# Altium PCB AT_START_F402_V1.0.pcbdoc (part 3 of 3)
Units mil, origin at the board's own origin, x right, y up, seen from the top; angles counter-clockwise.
Board outline 15424.54 x 3536.36 mil, 2 copper layers (Top Layer, Bottom Layer); 138 components, 133 nets, 522 pads, 730 vias.
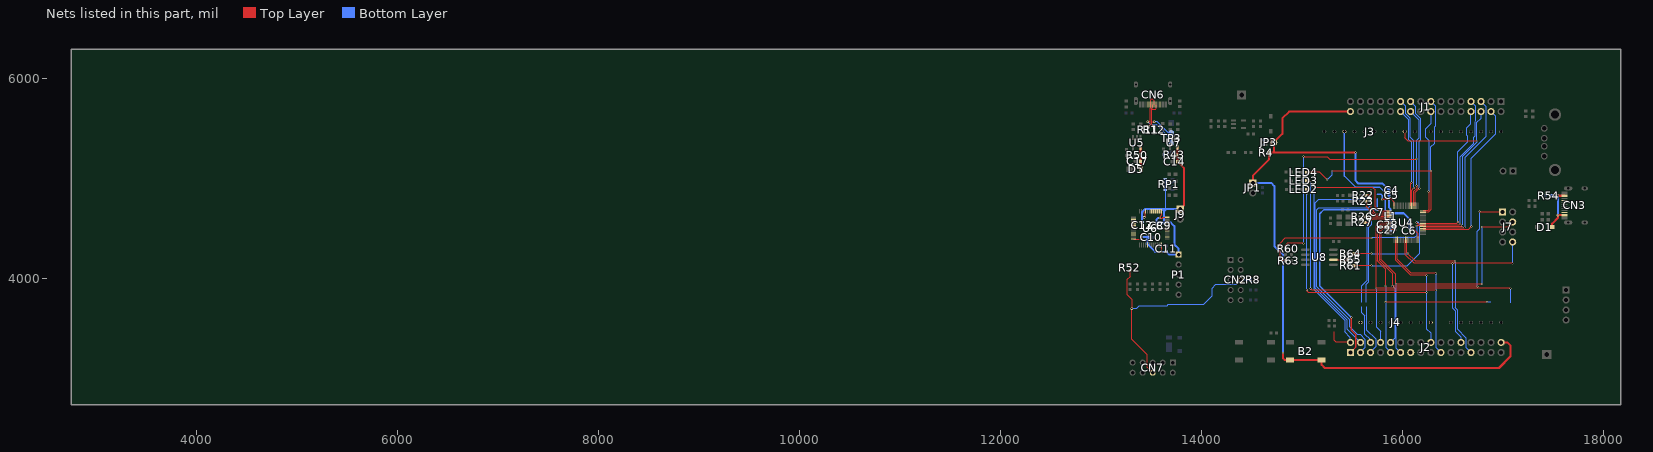
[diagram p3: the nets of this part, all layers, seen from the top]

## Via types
v1: diameter 19.68, hole 11.81, Top Layer to Bottom Layer, 621 vias
v2: diameter 19.69, hole 11.81, Top Layer to Bottom Layer, 42 vias
v3: diameter 19.7, hole 11.81, Top Layer to Bottom Layer, 26 vias
v4: diameter 23.62, hole 11.81, Top Layer to Bottom Layer, 17 vias
v5: diameter 27.56, hole 13.78, Top Layer to Bottom Layer, 15 vias
v6: diameter 24, hole 12, Top Layer to Bottom Layer, 7 vias
v7: diameter 27.56, hole 15.75, Top Layer to Bottom Layer, 2 vias

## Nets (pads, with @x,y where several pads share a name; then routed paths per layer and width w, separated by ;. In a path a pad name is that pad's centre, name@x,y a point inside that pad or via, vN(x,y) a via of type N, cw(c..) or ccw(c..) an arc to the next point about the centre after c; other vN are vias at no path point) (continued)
PB15: J1.4 U4.36 | length 1755.5
  Top Layer w6: U4.36@16206.86,4488.69 16654.71,4488.69 v1(16688.58,4522.56)
  Bottom Layer w6: v1(16688.58,4522.56) 16688.58,5200.56 16926.58,5438.56 16926.58,5622.73 J1.4@16883.44,5665.86
PC0: J2.8 U4.8 | length 2802.9
  Top Layer w6: U4.8@15868.28,4567.44 15779.45,4567.44 15739.58,4527.56 v1(15739.58,3907.2) 17075.94,3907.2 v1(17076.58,3906.57)
  Bottom Layer w6: v1(15739.58,3907.2) 15739.58,3522.95 15783.88,3478.65 J2.8@15783.88,3368.14 ; 17076.58,3763.97 v1(17076.58,3906.57)
PC1: J2.9 U4.9 | length 2479.8
  Top Layer w6: v1(15834.61,3768.57) v2(16842.58,3768.57) ; v1(15834.58,3928.57) 15834.58,4096.56 15752.58,4178.56 15752.58,4511.56 15792.7,4551.69 U4.9@15868.28,4551.69
  Bottom Layer w6: v1(15834.58,3928.57) v1(15834.61,3768.57) 15834.58,3317.45 J2.9@15883.88,3268.14 ; v2(16842.58,3768.57) 16880.08,3768.57 ; 16878.83,3769.82 16880.08,3768.57 ; 16881.83,3766.82 16880.08,3768.57
PC2: J2.10 J7.1 U4.10 | length 3155.1
  Top Layer w6: U4.10@15868.28,4535.94 15805.96,4535.95 15768.58,4498.56 15768.58,4187.56 15903.58,4052.57 v1(15903.58,3927.57) 16745.58,3927.57 v1(16746.58,3926.57) ; v1(16766.58,4669.56) 16996.47,4669.56 J7.1@16998.88,4667.16
  Bottom Layer w6: J2.10@15883.88,3368.14 15924.58,3408.84 15924.58,3906.57 v1(15903.58,3927.57) ; v1(16746.58,3926.57) 16746.58,4474.05 16766.58,4494.05 v1(16766.58,4669.56)
PC3: J2.11 J7.4 U4.11 | length 3150.1
  Top Layer w6: U4.11@15868.28,4520.19 15825.2,4520.19 15784.58,4479.56 15784.58,4197.03 15936.58,4045.03 v1(15936.58,3947.79) ; v1@15934.58,3949.79 v1(15936.58,3947.79) ; v1(16795.28,4517.56) 17049.28,4517.56 J7.4@17098.88,4567.16 ; v1(16795.58,3948.57) 16794.58,3947.57 15936.8,3947.57 v1(15936.58,3947.79)
  Bottom Layer w6: v1(15936.58,3947.79) 15936.58,3315.45 J2.11@15983.88,3268.14 ; v1(16795.28,4517.56) 16795.28,3948.86 v1(16795.58,3948.57)
PC4: J2.24 J7.8 U4.24 | length 2289.3
  Top Layer w6: U4.24@16029.7,4390.27 16029.7,4241.44 16116.58,4154.56 v2(16498.58,4154.56) v1(17099.58,4154.56)
  Bottom Layer w6: v2(16498.58,4154.56) 16498.58,3713.57 16526.58,3685.57 16526.58,3480.03 16583.88,3422.74 J2.24@16583.88,3368.14 ; J7.8@17098.88,4367.16 17099.58,4366.47 v1(17099.58,4154.56)
PC5: J2.25 R64.1 U4.25 | length 2155.2
  Top Layer w6: R64.1@15516.58,4251.56 v3(15691.58,4251.56) ; U4.25@16045.45,4390.27 16045.45,4261.69 v3(16055.57,4251.57) 16133.58,4173.56 v2(16525.58,4173.56)
  Bottom Layer w6: v3(15691.58,4251.56) v3(16055.57,4251.57) ; v2(16525.58,4173.56) 16525.58,3714.43 16544.58,3695.43 16544.58,3503.7 16632.58,3415.7 16632.58,3319.43 J2.25@16683.88,3268.14
PC6: J1.5 U4.37 | length 1773.5
  Top Layer w6: U4.37@16206.86,4504.44 16609.46,4504.44 v1(16619.58,4514.56)
  Bottom Layer w6: v1(16619.58,4514.56) 16619.58,5207.56 16828.58,5416.56 16828.58,5720.73 J1.5@16783.44,5765.86
PC7: J1.6 J3.2 U4.38 | length 2399.2
  Top Layer w6: J3.2@16023.88,5466.56 16023.88,5407.49 16060.81,5370.56 v2(16742.58,5370.56) ; U4.38@16206.86,4520.19 16585.21,4520.2 v1(16596.42,4531.41)
  Bottom Layer w6: v1(16596.42,4531.41) 16596.42,5215.93 16742.58,5362.08 v2(16742.58,5370.56) 16742.58,5559.56 16783.44,5600.44 J1.6@16783.44,5665.86
PC8: J1.7 R63.1 U4.39 | length 3447.9
  Top Layer w6: R63.1@14837.92,4181.56 14807.58,4181.56 14782.58,4206.56 14782.58,4355.56 14834.58,4407.56 v3(15691.58,4407.56) ; v3(16141.58,4525.56) 16151.95,4535.94 U4.39@16206.86,4535.94 16561.96,4535.95 v1(16575.22,4549.21)
  Bottom Layer w6: v3(15691.58,4407.56) 16119.58,4407.56 16141.58,4429.56 v3(16141.58,4525.56) ; v1(16575.22,4549.21) 16575.22,5218.21 16708.87,5351.85 16708.87,5408.23 16726.58,5425.94 16726.58,5566.56 16733.58,5573.56 16733.58,5717.56 16685.28,5765.86 J1.7@16683.44,5765.86
PC9: J1.8 R61.1 U4.40 | length 2627
  Top Layer w6: R61.1@15515.9,4131.56 v3(15692.58,4131.56) ; v3(16140.58,4562.56) 16151.45,4551.69 U4.40@16206.86,4551.69 16538.7,4551.69 v2(16553.58,4566.56)
  Bottom Layer w6: v3(15692.58,4131.56) 16051.58,4131.56 16173.58,4253.56 16173.58,4545.56 16156.58,4562.56 v3(16140.58,4562.56) ; v2(16553.58,4566.56) 16553.58,5265.56 16652.58,5364.56 16652.58,5418.56 16640.58,5430.56 16640.58,5503.56 16683.44,5546.44 J1.8@16683.44,5665.86
PC10: J1.19 U4.51 | length 1103.9
  Top Layer w6: U4.51@16124.19,4728.85 16124.19,4856.18 v2(16170.58,4902.56)
  Bottom Layer w6: J1.19@16083.44,5765.86 16134.58,5714.73 16134.58,5642.56 16184.58,5592.56 16184.58,5386.56 16170.58,5372.56 v2(16170.58,4902.56)
PC11: J1.20 R60.1 U4.52 | length 3218.6
  Top Layer w6: R60.1@14836.92,4300.56 14836.92,4334.9 14856.58,4354.56 v3(15015.58,4354.56) ; v3(15015.58,5217.56) 15253.58,5217.56 15278.49,5192.65 v3(16142.58,5192.65) ; U4.52@16108.44,4728.85 16108.44,4865.44 16142.58,4899.56 v2(16142.58,4930.56)
  Bottom Layer w6: v3(15015.58,4354.56) v3(15015.58,5217.56) ; J1.20@16083.44,5665.86 16168.58,5580.73 16168.58,5404.56 16142.58,5378.56 v3(16142.58,5192.65) v2(16142.58,4930.56)
PC12: J1.21 U4.53 | length 1100.4
  Top Layer w6: U4.53@16092.69,4728.85 16092.69,4884.68 v2(16114.58,4906.56)
  Bottom Layer w6: J1.21@15983.44,5765.86 16032.58,5716.73 16032.58,5644.56 16078.58,5598.56 16078.58,5412.56 16114.58,5376.56 v2(16114.58,4906.56)
PC13: J2.2 U4.2 | length 2911.7
  Top Layer w6: v1(15116.58,4912.56) 15702.58,4912.56 15728.58,4886.56 15728.58,4719.56 15786.22,4661.93 U4.2@15868.28,4661.93 ; 15317.85,3474.57 15322.76,3474.57 15320.58,3472.38 15320.58,3391.57 15344,3368.14 J2.2@15483.88,3368.14
  Bottom Layer w6: v1(15116.58,4912.56) 15116.58,3896.57 15425.58,3587.57 15425.58,3472.57 15483.88,3414.27 J2.2@15483.88,3368.14
PC14: J2.3 | length 2278.3
  Bottom Layer w6: J2.3@15583.88,3268.14 15633.58,3317.84 15633.58,3396.57 15586.58,3443.57 15554.58,3443.57 15475.58,3522.57 15475.58,3593.57 15147.58,3921.57 15147.58,4688.56 15169.58,4710.56 15659.58,4710.56 15689.58,4740.56 15689.58,4794.28
PC14/LEXT_IN: R22.1 U4.3 | length 480.3
  Top Layer w6: R22.1@15637.08,4832.56 15688.55,4832.56 ; v1(15688.58,4881.56) 15688.58,4696.56 15738.96,4646.18 U4.3@15868.28,4646.18
  Bottom Layer w6: v1(15688.58,4881.56) 15689.58,4880.56 15689.58,4838.69
PC15: J2.4 | length 2051.5
  Bottom Layer w6: J2.4@15583.58,3368.57 15450.58,3501.57 15450.58,3590.57 15132.58,3908.57 15132.58,4756.68 15170.18,4794.28 15593.58,4794.28
PC15/LEXT_OUT: R23.1 U4.4 | length 448.6
  Top Layer w6: R23.1@15639.08,4774.56 v1(15639.08,4739.92) 15639.08,4722.06 15730.71,4630.43 U4.4@15868.28,4630.43
  Bottom Layer w6: 15605.58,4838.69 15605.69,4838.56 15633.58,4838.56 15639.08,4833.06 v1(15639.08,4739.92)
PD2: J1.22 U4.54 | length 988.3
  Top Layer w6: U4.54@16076.94,4728.85 16076.94,4942.93 v2(16092.58,4958.56)
  Bottom Layer w6: J1.22@15983.58,5665.56 16064.58,5584.56 16064.58,5387.45 16092.58,5359.45 v2(16092.58,4958.56)
PF0: J2.5 | length 511.8
  Bottom Layer w6: 15643.58,3721.28 15642.58,3720.28 15642.58,3495.57 15733.58,3404.57 15733.58,3323.57 15683.88,3273.86 J2.5@15683.88,3268.14
PF0/HEXT_IN: R26.1 U4.5 | length 1120.8
  Top Layer w6: R26.1@15628.08,4616.56 15629.17,4615.47 v1(15671.97,4615.33) U4.5@15868.28,4614.69
  Bottom Layer w6: 15643.58,3765.68 15643.58,3948.57 15665.58,3970.57 15665.58,4513.56 15694.58,4542.56 15694.58,4592.72 v1(15671.97,4615.33)
PF1: J2.6 | length 393.2
  Bottom Layer w6: 15589.58,3722.28 15589.58,3670.57 15628.58,3631.57 15628.58,3447.57 15683.88,3392.26 J2.6@15683.88,3368.14
PF1/HEXT_OUT: R27.1 U4.6 | length 1084.7
  Top Layer w6: R27.1@15628.08,4562.56 v1(15670.58,4562.56) 15706.94,4598.94 U4.6@15868.28,4598.94
  Bottom Layer w6: 15589.58,3766.68 15589.58,3925.57 15647.58,3983.57 15647.58,4539.56 v1(15670.58,4562.56)
PF4: J2.18 LED2.2 U4.18 | length 3464.8
  Top Layer w6: v1(15049.23,3891.48) 15049.23,3881.04 15064.35,3865.91 v1(16240.58,3865.91) ; v1(15049.23,4849.22) 15049.53,4849.52 LED2.2@15049.53,4890.77 ; U4.18@15935.22,4390.27 15935.22,4185.93 16085.58,4035.57 v2(16240.58,4035.57)
  Bottom Layer w6: v1(15049.23,3891.48) v1(15049.23,4849.22) ; v2(16240.58,4035.57) v1(16240.58,3865.91) 16240.58,3506.57 16283.88,3463.28 J2.18@16283.88,3368.14
PF5: J2.19 LED3.2 U4.19 | length 3807.3
  Top Layer w6: LED3.2@15049.53,4976.77 v1(15085.37,4976.77) ; v1(15085.37,3904.35) 15102.48,3887.25 v1(16333.58,3887.25) ; U4.19@15950.97,4390.27 15950.97,4195.18 16090.58,4055.57 v2(16333.58,4055.57)
  Bottom Layer w6: v1(15085.37,3904.35) v1(15085.37,4976.77) ; v2(16333.58,4055.57) v1(16333.58,3887.25) 16333.58,3318.43 J2.19@16383.88,3268.14
PF6: J1.15 LED4.2 U4.47 | length 2527.9
  Top Layer w6: LED4.2@15049.53,5060.77 15179.37,5060.77 v1(15251.58,4988.56) ; v1(15302.58,5074.56) v2(16284.58,5074.56) 16284.58,4687.56 16258.93,4661.93 U4.47@16206.86,4661.93
  Bottom Layer w6: v1(15251.58,4988.56) 15302.58,5039.56 v1(15302.58,5074.56) ; J1.15@16283.44,5765.86 16332.58,5716.73 16332.58,5522.56 16322.58,5512.56 16322.58,5352.56 16284.58,5314.56 v2(16284.58,5074.56)
PF7: J1.16 U4.48 | length 1073.3
  Top Layer w6: U4.48@16206.86,4677.68 16252.69,4677.68 16261.58,4686.56 v2(16261.58,4870.56)
  Bottom Layer w6: v2(16261.58,4870.56) 16262.58,4871.56 16262.58,5382.56 16230.58,5414.56 16230.58,5490.56 16283.44,5543.44 J1.16@16283.44,5665.86
SCK: R65.2 U8.6 | length 143.2
  Top Layer w6: U8.6@15314.03,4191.56 R65.2@15457.25,4191.56
SWO: CN2.6 CN7.6 R8.2 R52.1 | length 2484.5
  Top Layer w6: R52.1@13290.15,4081.97 13290.15,4024.01 13256.58,3990.45 13256.58,3846.57 13306.58,3796.57 v4(13306.58,3704.57) 13306.58,3399.57 13462.58,3243.57 13462.58,3119.78 CN7.6@13515.34,3067.01
  Bottom Layer w6: v4(13306.58,3704.57) 13350.58,3704.57 13374.58,3728.57 13653.58,3728.57 13665.58,3740.57 14016.58,3740.57 14101.58,3825.57 14101.58,3904.57 14139.58,3942.57 14343.65,3942.57 CN2.6@14390.92,3989.84 ; CN2.6@14390.97,3989.89 R8.2@14490.58,3989.89
USB+: CN6.A6 CN6.B6 R11.1 TP3.3 | length 723.2
  Top Layer w11.2: v5(13466.68,5563.67) 13490.33,5563.67 ; R11.1@13469.58,5515.56 13490.33,5536.31 13490.33,5563.67 ; CN6.A6@13528.38,5735.27 13528.38,5774.77 13516.58,5786.56 13499.58,5786.56 13489.58,5776.56 13489.58,5735.77 CN6.B6@13489.08,5735.27 13489.08,5699.11 13490.33,5697.86 13490.33,5563.67
  Bottom Layer w11.2: v5(13466.68,5563.67) 13497.78,5532.56 13553.58,5532.56 13699.92,5386.22 TP3.3@13699.92,5351.02
USB-: CN6.A7 CN6.B7 R12.1 TP3.2 | length 554.9
  Top Layer w11.2: CN6.A7@13508.77,5735.27 13508.77,5699.11 13507.52,5697.86 13507.52,5683.94 ; R12.1@13528.58,5515.23 13507.52,5536.27 13507.52,5563.67 ; v5(13531.68,5563.67) 13507.52,5563.67 ; CN6.B7@13548.08,5735.27 13548.08,5693.06 13539.58,5684.56 13508.15,5684.56 13507.52,5683.94 ; 13507.52,5563.67 13507.52,5683.94
  Bottom Layer w11.2: v5(13531.68,5563.67) 13561.47,5563.67 13674.12,5451.02 TP3.2@13699.92,5451.02
VBUS_FS: CN3.A4B9 CN3.B4A9 D1.1 R54.2 | length 531.4
  Top Layer w20: D1.1@17492.58,4515.56 17492.58,4550.28 17549.08,4606.78 v6(17549.08,4635.06) CN3.A4B9@17615.28,4635.06 ; v6(17549.08,4827.06) 17550.08,4828.06 CN3.B4A9@17615.28,4828.06
  Bottom Layer w6: R54.2@17485.58,4827.56 v6@17548.58,4827.56
  Bottom Layer w20: v6@17548.58,4827.56 v6(17549.08,4827.06) v6(17549.08,4635.06)
VCC: C8.1 C9.1 C10.1 C11.1 C12.1 C14.1 J9.1 P1.1 R43.2 RP1.1 RP1.2 RP1.3 RP1.4 U6.1 U6.9 U6.24 U6.36 U6.48 U7.5 | length 3073.1
  Top Layer w10: U6.24@13324.5,4397.43 13390.33,4397.43 v4(13407.92,4415.02) ; v4(13430.58,4612.56) 13442.6,4624.6 U6.9@13442.6,4673.02 ; U6.36@13600.08,4338.36 13600.08,4270.27 v4(13600.34,4270.02) ; U6.1@13600.08,4673.02 13600.08,4632.76 13583.34,4616.02 v4(13583.34,4606.02) 13612.34,4606.02 13620.3,4613.97 U6.48@13659.15,4613.97
  Top Layer w20: C14.1@13764.14,5165.56 13827.58,5102.12 13827.58,4732.16 J9.1@13789.38,4693.97 ; C14.1@13764.34,5166.3 U7.5@13764.34,5307.9
  Bottom Layer w10: 13638.82,4683.98 13640.58,4685.73 13640.58,4694.02 RP1.1@13640.58,4887.56 RP1.2@13640.58,4922.99 RP1.3@13640.58,4958.44 RP1.4@13640.58,4993.86
  Bottom Layer w20: C12.1@13407.34,4560.02 13407.34,4664.02 13437.34,4694.02 13610.53,4694.02 ; 13407.35,4614.02 13429.12,4614.02 v4(13430.58,4612.56) ; v4(13407.92,4415.02) 13465.34,4415.02 13465.34,4345.02 13540.34,4270.02 v4(13600.34,4270.02) 13650.58,4273.06 13681.08,4242.56 P1.1@13772.58,4242.56 13772.58,4300.56 13730.34,4342.8 13730.34,4526.02 13696.34,4560.02 C9.1@13628.34,4560.02 ; v4(13583.34,4606.02) 13567.34,4606.02 13554.34,4593.02 13554.34,4560.02 C9.1@13628.34,4560.02 ; J9.1@13789.34,4694.02 13649.06,4694.02 ; 13610.53,4694.02 13610.53,4691.52 13628.34,4673.7 ; 13610.53,4694.02 13640.58,4694.02 13649.06,4694.02 ; C9.1@13628.34,4560.02 13628.34,4673.7 ; 13628.34,4673.7 13638.82,4683.98 13649.06,4694.02
VCC3.5V: C17.1 D5.2 R50.2 U5.5 | length 488.1
  Top Layer w20: U5.5@13395.58,5305.56 13395.15,5110.74 D5.2@13396.33,5109.56
  Top Layer w25: D5.2@13389.33,5099.56 D5.2@13395.14,5105.38 ; U5.5@13395.14,5305.9 C17.1@13395.14,5173.56 ; D5.2@13397.33,5091.56 13395.14,5093.76 D5.2@13395.14,5105.38 ; D5.2@13395.15,5105.39 13395.15,5110.74 C17.1@13395.14,5173.56 ; D5.2@13395.14,5105.38 C17.1@13395.14,5173.56
VDD: B2.1 B2.2 C4.1 C5.1 C6.1 C7.1 J1.32 J2.1 J2.32 JP1.1 JP3.2 L1.1 R4.1 U4.1 U4.32 U4.64 | length 10874.9
  Top Layer w8: v1(15792.58,4690.56) 15805.47,4677.68 U4.1@15868.28,4677.68 ; v1(15869.11,4792.31) 15869.37,4792.56 15892.58,4792.56 15919.47,4765.68 U4.64@15919.47,4728.85 ; v1(16108.58,4499.56) 16155.68,4452.45 U4.32@16155.68,4403.27
  Top Layer w15: J2.1@15483.88,3268.14 15534.58,3318.84 15534.58,3446.57 15493.58,3487.57 v1(15493.58,3614.57) ; v1@15799.58,4792.56 v1(15799.83,4792.31) v1(15869.11,4792.31)
  Top Layer w20: JP1.1@14511.57,4956.56 14511.57,5028.56 14675.08,5192.06 R4.1@14675.08,5258.56 14720.43,5258.56 14720.58,5258.71 ; v1(14813.58,3262.57) 14813.58,3209.57 14830.58,3192.57 14880.68,3192.57 B2.2@14881.09,3192.99 B2.1@15196.06,3192.99 15196.06,3144.09 15226.58,3113.57 16962.58,3113.57 17076.58,3227.57 17076.58,3338.57 17046.58,3368.57 16984.31,3368.57 J2.32@16983.88,3368.14 ; J1.32@15483.44,5665.86 14873.88,5665.86 14806.58,5598.56 14806.58,5444.56 JP3.2@14720.58,5358.57 14720.58,5258.71 ; v1(15532.72,5258.71) 14720.58,5258.71
  Bottom Layer w15: v1(15493.58,3614.57) 15177.58,3930.57 15177.58,4647.84 15216.3,4686.56 15746.08,4686.56 C7.1@15750.58,4691.06 ; 15750.58,4796.28 C7.1@15750.58,4691.06 ; 15750.58,4840.69 15790.45,4840.69 15799.83,4831.31 v1(15799.83,4792.31) ; v1(15792.58,4690.56) 15751.08,4690.56 C7.1@15750.58,4691.06
  Bottom Layer w20: JP1.1@14511.57,4956.56 14694.58,4956.56 14726.58,4924.56 14726.58,4327.56 14813.58,4240.56 v1(14813.58,3262.57) ; v1(15532.72,5258.71) 15532.72,4980.88 15564.04,4949.56 15804.08,4949.56 C4.1@15869.08,4884.56 v1(15869.11,4792.31) ; 15869.08,4809.56 v1(15869.11,4792.31) ; v1(16108.58,4499.56) 16099.08,4509.06 C6.1@16069.58,4509.06 16069.58,4598.56 16014.26,4653.88 L1.1@15884.58,4653.88 15883.58,4654.88 15883.58,4694.56 15869.11,4709.03 v1(15869.11,4792.31)
VDDA: C27.2 C28.2 J3.8 L1.2 U4.13 | length 1446
  Top Layer w9: U4.13@15868.28,4488.69 15868.41,4488.56 v2(15933.58,4488.56)
  Bottom Layer w15: J3.8@15423.88,5466.56 15423.88,5023.91 15533.22,4914.56 15773.58,4914.56 15832.58,4855.56 15832.58,4607.56 15846.9,4593.24 L1.2@15884.58,4593.24 C28.2@15884.58,4537.56 ; C27.2@15884.58,4488.56 v2(15933.58,4488.56)
  Bottom Layer w20: C27.2@15884.58,4488.56 C28.2@15884.58,4537.56
"": CN3.A8 CN3.B8 CN6.A8 CN6.B8 J2.13 J4.1 J4.8 U6.2 U6.3 U6.4 U6.5 U6.6 U6.14 U6.15 U6.16 U6.17 U6.18 U6.21 U6.22 U6.29 U6.38 U6.41 U6.42 U6.43 U6.45 U6.46

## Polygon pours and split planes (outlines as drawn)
GND on Bottom Layer (solid, remove dead copper, pour order 0): 17151.58,5987.56 17151.58,5631.4 17408.58,5629.56 17455.58,5607.56 17455.58,4872.56 17699.58,4872.56 17699.58,4588.86 17594.58,4586.56 17595.17,4511.56 17700.57,4512.19 17701.58,3042.57 13183.5,3041.64 13182.58,3042.57 13182.58,5728.56 13368.58,5728.56 13368.58,5808.56 13373.58,5813.56 13662.58,5813.56 13662.58,5732.56 13939.58,5732.56 13939.58,5984.56 13942.98,5987.97 17151.17,5987.97
GND on Bottom Layer (solid, remove dead copper, pour order 1): 17604.57,4095.86 17604.58,4095.57 17604.58,4096.56
GND on Top Layer (solid, remove dead copper, pour order 2): 17151.58,5681.37 17151.58,5632.56 17151.54,5681.37
GND on Top Layer (solid, remove dead copper, pour order 3): 17151.58,5987.56 17151.58,5632.56 17408.58,5629.56 17455.58,5607.56 17455.58,4872.56 17699.83,4872.27 17699.58,4592.56 17699.58,4588.56 17595.58,4586.56 17595.58,4511.56 17700.58,4511.56 17700.58,3970.57 17701.58,3042.57 13182.58,3042.57 13182.58,5727.56 13181.58,5728.56 13368.58,5728.56 13368.58,5793.28 13348.48,5813.38 13662.39,5813.38 13662.58,5813.56 13662.58,5732.56 13940.58,5732.56 13940.58,5985.56 13942.58,5987.56

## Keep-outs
Top Layer:
  region net "": 13642.58,4450.56 13675.58,4450.56 13675.58,4443.56 13642.58,4443.56
Board Outline Layer:
  lines w8 net "": 13799.95,3001.67 ccw(c13802.87,3080.36) 13881.61,3080.36 13881.87,3519.01 13921.13,3519.01 13921.13,3080.36 ccw(c13999.87,3080.36) 13999.87,3001.62 ; 13802.87,6030.91 cw(c13802.87,5952.17) 13881.61,5952.17 13881.61,5632.02 13921.13,5632.02 13921.13,5951.91 cw(c13999.87,5951.91) 13999.87,6030.65 ; 13920.13,4826.02 13881.87,4826.02 13881.87,3810.02 ; 13920.87,4825.28 13920.87,3810.01 13881.87,3810.01 ; 13999.24,3001.05 ccw(c13999.87,3005.02) 13999.87,3001 ; 13999.87,6031.43 ccw(c13999.9,6035.44) 13999.9,6031.43 ; 17836.3,5974.43 cw(c17836.87,5970.45) 17836.87,5974.47 ; 13881.87,3810.02 13881.87,3810.01 ; 13881.87,3607.01 13881.87,3699.01 13921.13,3699.01 13921.13,3607.01 13881.87,3607.01 ; 13881.87,4904.02 13881.87,5554.02 13921.13,5554.02 13921.13,4904.27 13920.87,4904.02 13881.87,4904.02
  lines w10 net "": 13149.49,5947.67 cw(c13153.5,5947.67) 13150.15,5949.89 cw(c13232.87,5947.41) 13231.42,6030.16 cw(c13232.87,6026.41) 13232.87,6030.43 ; 13149.49,5947.67 13149.49,5947.67 ; 13149.49,5947.67 13149.9,3082.97 ; 13149.9,3082.97 13149.9,3082.97 ; 13149.9,3082.97 ccw(c13153.92,3082.97) 13150.17,3081.52 ccw(c13232.92,3082.97) 13231.59,3000.23 ccw(c13232.92,3004.02) 13232.92,3000 ; 13232.87,6030.43 13999.81,6030.43 13999.87,6030.43 17281.13,6030.43 17836.3,6030.43 17836.87,6030.47 cw(c17836.87,5947.71) 17919.61,5949.17 cw(c17915.87,5947.71) 17919.89,5947.71 ; 13232.87,6030.43 13232.87,6030.43 ; 13232.92,3000 13232.92,3000 ; 13232.92,3000 13998.61,3000 ; 13998.61,3000 13998.61,3000 ; 13998.61,3000 ccw(c13998.61,3004.02) 13999.24,3000.05 13999.87,3000 17281.13,3000 17836.87,3000 ; 17836.87,3000 17836.87,3000 ; 17836.87,3000 ccw(c17836.87,3082.76) 17919.61,3081.3 ccw(c17915.87,3082.76) 17919.88,3082.76 ; 17919.88,3082.76 17919.88,3082.76 ; 17919.88,3082.76 17919.88,5947.72 ; 17919.88,5947.72 17919.89,5947.71

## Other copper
Top Layer:
  drawing of 487 lines, arcs and shapes, not listed
Bottom Layer:
  drawing of 388 lines, arcs and shapes, not listed

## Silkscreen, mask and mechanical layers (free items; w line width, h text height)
Top Silkscreen Layer:
  circle w50 net "": c17073.58,5765.56 r1
  circle w50 net "": c15389.58,3268.57 r1
  lines w5 net "": 16867.58,5338.56 16869.58,5338.56 ; 17005.58,5355.56 17003.58,5355.56 ; 16869.58,5338.56 16888.58,5357.56 16888.58,5362.56 ; 16869.58,5338.56 16905.58,5338.56 ; 16869.58,5338.56 16871.58,5338.56 16888.58,5355.56 ; 16888.58,5338.56 16885.58,5341.56 16874.58,5341.56 16875.58,5340.56 16880.58,5340.56 16887.08,5347.06 16888.58,5347.06 16897.08,5338.56 16905.58,5338.56 ; 16888.58,5338.56 16888.58,5355.56 ; 16888.58,5338.56 16893.58,5343.56 ; 16888.58,5355.56 16893.58,5350.56 16893.58,5343.56 ; 16888.58,5355.56 16908.58,5335.56 ; 16888.58,5355.56 16888.58,5362.56 ; 16888.58,5362.56 16886.58,5362.56 16859.58,5335.56 16908.58,5335.56 ; 16888.58,5362.56 16915.58,5335.56 16908.58,5335.56 ; 16893.58,5343.56 16900.58,5343.56 16905.58,5338.56 ; 16905.58,5338.56 16908.58,5335.56 ; 16964.58,5358.56 17013.58,5358.56 16986.58,5331.56 16984.58,5331.56 ; 16964.58,5358.56 16957.58,5358.56 16984.58,5331.56 ; 16964.58,5358.56 16967.58,5355.56 ; 16964.58,5358.56 16984.58,5338.56 ; 16967.58,5355.56 16976.08,5355.56 16984.58,5347.06 16986.08,5347.06 16992.58,5353.56 16997.58,5353.56 16998.58,5352.56 16987.58,5352.56 16984.58,5355.56 ; 16967.58,5355.56 16972.58,5350.56 16979.58,5350.56 ; 16967.58,5355.56 17003.58,5355.56 ; 16979.58,5350.56 16984.58,5355.56 ; 16979.58,5350.56 16979.58,5343.56 16984.58,5338.56 ; 16984.58,5331.56 16984.58,5338.56 ; 16984.58,5331.56 16984.58,5336.56 17003.58,5355.56 ; 16984.58,5338.56 16984.58,5355.56 ; 16984.58,5338.56 17001.58,5355.56 17003.58,5355.56
  lines w6 net "": 13364.57,3293.28 13364.57,3592.28 ; 13464.57,3294.28 13464.57,3593.28 ; 13564.57,3294.28 13564.57,3594.28 ; 13666.57,3293.28 13666.57,3587.28
  lines w8 net "": 13462.92,3219.01 13462.92,3259.01 13562.92,3259.01 13562.92,3218.01 ; 13753.47,3273.01 13716.47,3236.01 13677.47,3275.01 13753.47,3275.01 ; 14177.57,4227.19 14177.57,4151.19 14216.57,4190.19 14179.57,4227.19 ; 14240.57,3940.2 14200.57,3940.2 14200.57,4040.2 14241.57,4040.2
  lines w10 net "": 15596.17,5193.72 17011.87,5193.72 ; 15870.08,3854.57 16323.08,3854.57 ; 16458.58,3854.57 17018.58,3854.57
  text "43" at 16450.01,5950.73 h38.28
  text "33" at 16956.01,5950.73 h38.28
  text "53" at 15956.01,5948.73 h38.28
  text "63" at 15450.01,5946.73 h38.28
  text "F6" at 16277.73,5839.29 h34.45 r45
  text "A8" at 16574.84,5837.58 h34.45 r45
  text "C8" at 16672.84,5837.58 h34.45 r45
  text "C12" at 15974.55,5837.29 h34.45 r45
  text "A12*" at 16367.51,5836.98 h34.45 r45
  text "A10" at 16466.55,5837.29 h34.45 r45
  text "B7" at 15684.84,5835.58 h34.45 r45
  text "B5" at 15780.52,5835.26 h34.45 r45
  text "B3" at 15876.78,5835.28 h34.45 r45
  text "B14" at 16872.55,5835.29 h34.45 r45
  text "B8" at 15578.84,5833.58 h34.45 r45
  text "C6" at 16778.84,5833.58 h34.45 r45
  text "C10" at 16068.55,5833.29 h34.45 r45
  text "A14" at 16162.55,5833.29 h34.45 r45
  text "B12" at 16978.55,5833.29 h34.45 r45
  text "GND" at 15467.07,5826.52 h34.45 r45
  text "GND" at 14497.65,5812.28 h45.94
  text "B9" at 15572.84,5539.58 h34.45 r45
  text "F11" at 15661.9,5536.78 h28.71 r45
  text "F7" at 16271.74,5535.29 h34.45 r45
  text "D2" at 15977.46,5534.13 h34.45 r45
  text "C9" at 16674.84,5533.58 h34.45 r45
  text "C11" at 16069.87,5533.27 h34.45 r45
  text "A9" at 16574.84,5531.58 h34.45 r45
  text "C7" at 16774.84,5531.58 h34.45 r45
  text "B6" at 15774.53,5531.26 h34.45 r45
  text "B4" at 15870.8,5531.28 h34.45 r45
  text "A15" at 16168.55,5525.29 h34.45 r45
  text "B15" at 16864.55,5525.29 h34.45 r45
  text "B13" at 16976.55,5525.29 h34.45 r45
  text "A13" at 16362.55,5523.29 h34.45 r45
  text "A11*" at 16464.26,5523 h34.45 r45
  text "VDD" at 15446.55,5515.29 h34.45 r45
  text "4" at 16601.8,5362.56 h45.56 r90
  text "7" at 16313.8,5360.56 h45.56 r90
  text "2" at 16803.8,5360.56 h45.56 r90
  text "8" at 16147.8,5359.56 h45.56 r90
  text "13" at 15653.98,5333.59 h45.94 r90
  text "12" at 15747.98,5333.59 h45.94 r90
  text "IDD" at 14793.42,5328.4 h45.94
  text "#3" at 16709.98,5315.89 h45.94 r90
  text "#9" at 16047.98,5313.89 h45.94 r90
  text "#6" at 16405.98,5313.89 h45.94 r90
  text "#5" at 16509.98,5313.89 h45.94 r90
  text "#11" at 15851.98,5305.54 h45.94 r90
  text "#10" at 15947.98,5285.84 h45.94 r90
  text "HOST" at 17306.86,5274.63 h45.94 r90
  text "SCL" at 15245.98,5270.64 h45.94 r90
  text "GND" at 15547.98,5266.24 h45.94 r90
  text "SDA" at 15349.98,5264.04 h45.94 r90
  text "TX 1" at 16906.86,5234.63 h45.94 r90
  text "RX 0" at 17008.86,5231.63 h45.94 r90
  text "DIGITAL(#=PWM)" at 15992.19,5222.83 h40.19
  text "VDDA" at 15445.98,5214.18 h45.94 r90
  text "LD:" at 13803.32,5157 h40.19 r270
  text "AT-Link-EZ V1.4" at 13197.82,5072.38 h57.42 r270
  text "1" at 13803.99,5055.27 h39.87 r270
  text "FS_VBUS" at 16604.58,5055.28 h45.94
  text "2" at 13803.99,4988.27 h39.87 r270
  text "VDD" at 14300.65,4945.28 h45.95
  text "3" at 13803.99,4915.27 h39.87 r270
  text "4" at 13803.99,4840.27 h39.87 r270
  text "BOOT0" at 14204.62,4833.28 h45.94
  text "5V" at 17172.91,4650.31 h40.19
  text "MISO" at 16783.02,4648.83 h40.19
  text "Device" at 17541.86,4612.59 h45.94 r90
  text "SCK" at 16803.5,4543.83 h40.19
  text "MOSI" at 17169.02,4543.83 h40.19
  text "GND" at 17169.5,4448.83 h40.19
  text "RESET" at 16732.53,4443.83 h40.19
  text "NSS" at 16803.5,4343.83 h40.19
  text "PC4" at 17169.78,4338.83 h40.19
  text "AT-Link" at 14180.76,4295.65 h57.42
  text "5V" at 14477.98,4173.83 h40.19
  text "3V3" at 14041.5,4167.83 h40.19
  text "SWD" at 14045.5,4073.83 h40.19
  text "BOOT0" at 14476.53,4068.83 h40.19
  text "SWO" at 14477.5,3968.83 h40.19
  text "SWC" at 14042.5,3958.83 h40.19
  text "AT-START-F402 V1.0" at 16034.71,3911.41 h69.7
  text "3V3" at 17437.83,3868.83 h40.19
  text "USART1_RX" at 14474.6,3863.83 h40.19
  text "NRST" at 14047.02,3858.83 h40.19
  text "POWER" at 16104.53,3790.83 h40.19
  text "ANALOG IN" at 16606.6,3790.83 h40.19
  text "USART1_TX" at 17201.23,3772.83 h40.19
  text "GND" at 14047.5,3768.83 h40.19
  text "USART1_TX" at 14474.6,3763.83 h40.19
  text "USART1_RX" at 17200.23,3667.83 h40.19
  text "AN0" at 16507.28,3641.49 h45.94 r90
  text "AN1" at 16603.28,3641.49 h45.94 r90
  text "AN2" at 16708.28,3640.49 h45.94 r90
  text "AN3" at 16809.28,3640.49 h45.94 r90
  text "AN4" at 16911.28,3640.49 h45.94 r90
  text "AN5" at 17011.28,3640.49 h45.94 r90
  text "IOREF" at 15705.98,3638.23 h45.94 r90
  text "5V" at 16003.98,3637.89 h45.94 r90
  text "RESET" at 15802.98,3637.23 h45.94 r90
  text "3.3V" at 15903.98,3636.78 h45.94 r90
  text "GND" at 16104.98,3637.34 h45.94 r90
  text "GND" at 16204.27,3637.34 h45.94 r90
  text "SWD" at 13594.85,3591.93 h40.19 r270
  text "GND" at 13290.84,3587.64 h40.19 r270
  text "NRST" at 13390.84,3588.12 h40.19 r270
  text "SWC" at 13495.84,3587.64 h40.19 r270
  text "3V3" at 13690.84,3587.64 h40.19 r270
  text "GND" at 17439.83,3570.83 h40.19
  text "F4" at 16273.74,3439.29 h34.45 r45
  text "B0" at 16656.16,3438.73 h34.45 r45
  text "B2" at 16761.96,3438.71 h34.45 r45
  text "A0" at 16072.16,3437.56 h34.45 r45
  text "A2" at 16165.99,3437.56 h34.45 r45
  text "A4" at 16364.11,3437.56 h34.45 r45
  text "A6" at 16457.93,3437.56 h34.45 r45
  text "F1*" at 15684.55,3437.29 h34.45 r45
  text "C0" at 15776.53,3435.26 h34.45 r45
  text "C2" at 15872.8,3435.28 h34.45 r45
  text "C4" at 16554.17,3435.26 h34.45 r45
  text "B11" at 16862.16,3432.62 h34.45 r45
  text "C13" at 15463.09,3426.52 h34.45 r45
  text "BOOT0" at 13599.28,3423.1 h30.14 r270
  text "C15*" at 15570.26,3423 h34.45 r45
  text "SWO" at 13496.83,3422.35 h40.19 r270
  text "GND" at 15968.16,3421.82 h34.45 r45
  text "VDD" at 16972.16,3421.82 h34.45 r45
  text "RX" at 13289.83,3398.87 h40.19 r270
  text "TX" at 13390.84,3397.57 h40.19 r270
  text "5V" at 13689.83,3397.57 h40.19 r270
  text "GND" at 17525.65,3224.28 h45.94
  text "C1" at 15880.84,3143.58 h34.45 r45
  text "A1" at 16176.16,3142.07 h34.45 r45
  text "NC" at 16076.84,3137.58 h34.45 r45
  text "F5" at 16368.84,3137.58 h34.45 r45
  text "B1" at 16776.84,3137.58 h34.45 r45
  text "C3" at 15974.84,3135.58 h34.45 r45
  text "C5" at 16666.84,3133.58 h34.45 r45
  text "A3" at 16260.75,3132.8 h34.45 r45
  text "A7" at 16568.84,3131.58 h34.45 r45
  text "F0*" at 15664.55,3129.29 h34.45 r45
  text "A5" at 16462.84,3127.58 h34.45 r45
  text "B10" at 16858.55,3119.29 h34.45 r45
  text "C14*" at 15556.26,3115 h34.45 r45
  text "VDD" at 15442.16,3112.82 h34.45 r45
  text "GND" at 16954.55,3113.29 h34.45 r45
  text "NRST" at 15734.26,3089 h34.45 r45
  text "RESET" at 14433.54,3078.31 h45.94
  text "USER" at 14956.09,3077.31 h45.94
  text "21" at 16463.01,3053.72 h38.28
  text "31" at 16962.01,3052.72 h38.28
  text "11" at 15969.01,3051.72 h38.28
  text "1" at 15475.58,3048.88 h37.97
Bottom Silkscreen Layer:
  text "61" at 15556.74,5819.69 h38.28 r315
  text "59" at 15665.74,5819.69 h38.28 r315
  text "57" at 15766.74,5819.69 h38.28 r315
  text "55" at 15864.74,5819.69 h38.28 r315
  text "53" at 15965.74,5819.69 h38.28 r315
  text "51" at 16065.74,5819.69 h38.28 r315
  text "39" at 16666.74,5819.69 h38.28 r315
  text "37" at 16767.74,5819.69 h38.28 r315
  text "35" at 16866.74,5819.69 h38.28 r315
  text "33" at 16971.74,5819.69 h38.28 r315
  text "63" at 15457.74,5814.69 h38.28 r315
  text "49" at 16168.74,5814.69 h38.28 r315
  text "43" at 16468.74,5814.69 h38.28 r315
  text "47" at 16265.74,5812.69 h38.28 r315
  text "45" at 16363.74,5812.69 h38.28 r315
  text "41" at 16566.74,5812.69 h38.28 r315
  text "64" at 15469.74,5544.69 h38.28 r315
  text "62" at 15569.74,5544.69 h38.28 r315
  text "60" at 15669.74,5544.69 h38.28 r315
  text "58" at 15774.74,5544.69 h38.28 r315
  text "50" at 16176.74,5544.69 h38.28 r315
  text "34" at 16975.74,5544.69 h38.28 r315
  text "52" at 16076.74,5543.69 h38.28 r315
  text "44" at 16478.74,5543.69 h38.28 r315
  text "42" at 16575.74,5543.69 h38.28 r315
  text "38" at 16776.74,5543.69 h38.28 r315
  text "36" at 16878.74,5543.69 h38.28 r315
  text "48" at 16281.74,5542.69 h38.28 r315
  text "46" at 16379.74,5542.69 h38.28 r315
  text "40" at 16677.74,5542.69 h38.28 r315
  text "56" at 15876.74,5539.69 h38.28 r315
  text "54" at 15976.74,5539.69 h38.28 r315
  text "VDD" at 13667.79,4637.62 h34.45 r270
  text "AT32F402RCT7-7" at 16719.3,4050.85 h114.84
  text "GND" at 13654.79,3787.62 h34.45 r270
  text "2" at 15466.17,3435.85 h37.97 r315
  text "8" at 15764.17,3434.2 h37.97 r315
  text "4" at 15564.17,3432.2 h37.97 r315
  text "6" at 15660.17,3432.2 h37.97 r315
  text "10" at 15867.74,3423.69 h38.28 r315
  text "12" at 15969.74,3423.69 h38.28 r315
  text "16" at 16167.74,3423.69 h38.28 r315
  text "14" at 16065.74,3421.69 h38.28 r315
  text "18" at 16262.74,3421.69 h38.28 r315
  text "20" at 16364.74,3420.69 h38.28 r315
  text "22" at 16471.74,3420.69 h38.28 r315
  text "24" at 16572.74,3420.69 h38.28 r315
  text "26" at 16669.74,3419.69 h38.28 r315
  text "28" at 16777.74,3419.69 h38.28 r315
  text "32" at 16971.74,3416.69 h38.28 r315
  text "30" at 16874.74,3415.69 h38.28 r315
  text "1" at 15456.17,3167.85 h37.97 r315
  text "5" at 15654.17,3166.2 h37.97 r315
  text "9" at 15856.17,3166.2 h37.97 r315
  text "3" at 15545.44,3164.38 h37.97 r315
  text "7" at 15752.17,3164.2 h37.97 r315
  text "11" at 15955.74,3163.69 h38.28 r315
  text "19" at 16367.74,3160.69 h38.28 r315
  text "15" at 16167.74,3159.69 h38.28 r315
  text "13" at 16066.74,3158.69 h38.28 r315
  text "21" at 16469.74,3158.69 h38.28 r315
  text "31" at 16971.74,3156.58 h38.28 r315
  text "17" at 16269.74,3155.69 h38.28 r315
  text "29" at 16884.74,3151.69 h38.28 r315
  text "25" at 16681.74,3148.69 h38.28 r315
  text "23" at 16580.74,3147.69 h38.28 r315
  text "27" at 16777.74,3145.69 h38.28 r315
Mechanical Layer:
  circle w1 net "": c17792.21,5903.56 r62.99
  circle w1 net "": c17791.58,3128.57 r62.99
  circle w1 net "": c14044.58,3128.57 r62.99
  circle w1 net "": c14044.58,5903.56 r62.99
  circle w1 net "": c17083.58,4866.56 r62.99
  circle w1 net "": c15033.58,3566.57 r62.99
  circle w1 net "": c15083.58,5466.56 r62.99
